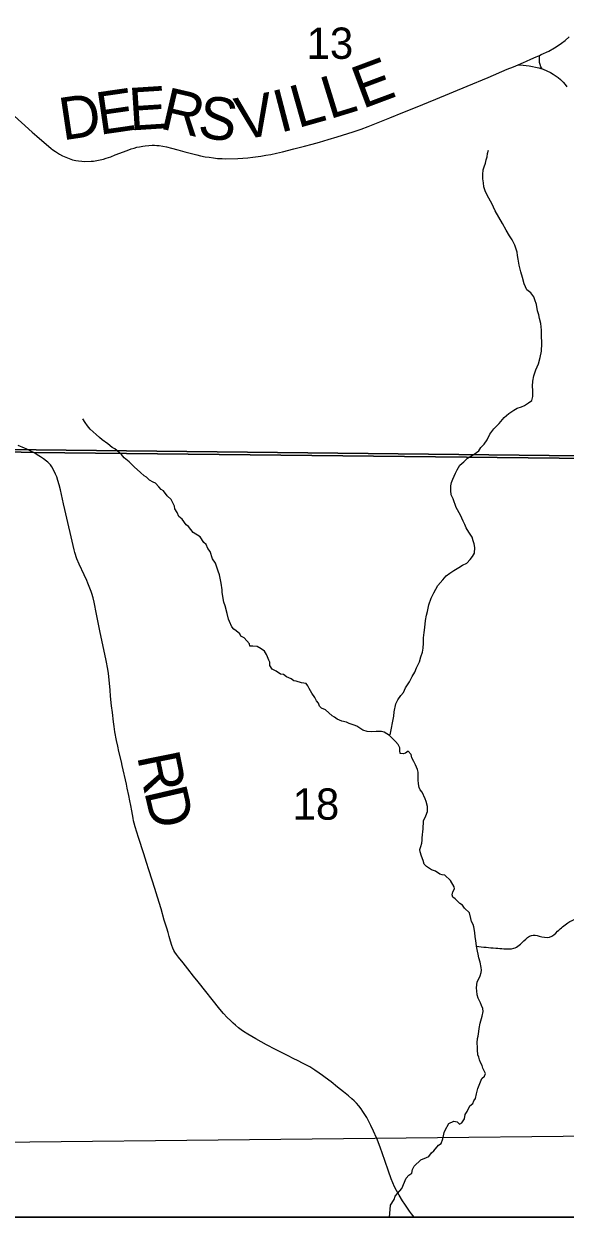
# Model space of a CAD drawing. Extents: x 0 to 34, y 0 to 22.
# Drawn here: x 21.301 to 22.024, y 13.6 to 15.196 of the extents above; entities that cross this region are included whole.
import ezdxf

# ---------------------------------------------------------------- set-up
doc = ezdxf.new("R2010")
doc.units = 0
for name, color, linetype in [('GM_X_Corporation', 7, 'Continuous'), ('GM_X_County_Road', 7, 'Continuous'), ('GM_X_County_Road_Text', 7, 'Continuous'), ('GM_X_Minor_River', 7, 'Continuous'), ('GM_X_Section_Text', 7, 'Continuous'), ('GM_X_Township_Road', 7, 'Continuous'), ('GM_X_Township_Road_Text', 7, 'Continuous'), ('SH_Data', 7, 'Continuous')]:
    doc.layers.add(name, color=color, linetype=linetype)

msp = doc.modelspace()

# ---------------------------------------------------------------- linework, layer by layer
at = {"layer": 'GM_X_Corporation'}
msp.add_lwpolyline([(20.2208, 16.9558), (20.1987, 15.2691), (20.203, 14.81), (20.2016, 14.6512), (20.2571, 14.6508), (21.1282, 14.6279), (21.314, 14.623), (22.3464, 14.612), (22.9003, 14.6033), (24.2301, 14.5912), (24.2265, 14.4444), (24.4406, 14.442), (25.338, 14.4317), (25.4, 14.4307), (25.4, 19.0068)], dxfattribs=at)
for points in [[(22.2224, 15.6282), (22.2045, 14.6168), (21.1958, 14.6279), (21.2159, 15.6439)], [(18.6, 14.6606), (18.6, 13.6), (24.2109, 13.6), (24.2228, 14.2453), (24.2265, 14.4444), (24.2301, 14.5912), (22.9003, 14.6033), (22.3464, 14.612), (21.314, 14.623), (21.1282, 14.6279), (20.2571, 14.6508), (20.2016, 14.6512), (19.8855, 14.6528), (19.4007, 14.6554), (18.9216, 14.6592)], [(21.1958, 14.6279), (22.2045, 14.6168), (22.1889, 13.7096), (21.1828, 13.6991)], [(21.1814, 13.6), (22.1867, 13.6), (22.1889, 13.7096), (21.1828, 13.6991)]]:
    msp.add_lwpolyline(points, close=True, dxfattribs=at)
at = {"layer": 'GM_X_County_Road'}
for points in [[(21.9616, 15.1415), (21.9686, 15.1447), (21.9724, 15.1464), (21.9783, 15.149), (21.9853, 15.1521), (21.9899, 15.1542), (21.992, 15.1552), (22.0025, 15.1601), (22.01, 15.1644), (22.0149, 15.1675), (22.0194, 15.1706), (22.024, 15.174), (22.0296, 15.179)], [(21.9933, 15.1362), (21.9918, 15.139), (21.9907, 15.1419), (21.9901, 15.1448), (21.9898, 15.1478), (21.9897, 15.1512), (21.9899, 15.1542)], [(21.2836, 15.0774), (21.3119, 15.0517), (21.3182, 15.0463), (21.3375, 15.0297), (21.3396, 15.0281), (21.3429, 15.0257), (21.347, 15.0229), (21.3486, 15.0221), (21.3525, 15.0199), (21.3567, 15.0179), (21.3615, 15.0161), (21.3658, 15.0147), (21.3703, 15.0137), (21.374, 15.013), (21.3783, 15.0125), (21.3825, 15.0123), (21.3908, 15.0125), (21.3937, 15.0129), (21.3982, 15.0136), (21.4028, 15.0145), (21.4071, 15.0156), (21.4107, 15.0168), (21.417, 15.0187), (21.4227, 15.0212), (21.4388, 15.027), (21.4443, 15.029), (21.4481, 15.0302), (21.4519, 15.0313), (21.4554, 15.0321), (21.4596, 15.0328), (21.463, 15.0333), (21.4678, 15.0338), (21.4722, 15.034), (21.4754, 15.0339), (21.4787, 15.0338), (21.4817, 15.0335), (21.4864, 15.0329), (21.4913, 15.0319), (21.498, 15.0302), (21.5064, 15.028), (21.5158, 15.0254), (21.5266, 15.0225), (21.5321, 15.021), (21.5369, 15.02), (21.5431, 15.0187), (21.5486, 15.0179), (21.5544, 15.017), (21.5598, 15.0165), (21.5659, 15.0161), (21.5706, 15.016), (21.5868, 15.0163), (21.5936, 15.0167), (21.6002, 15.0173), (21.607, 15.018), (21.6176, 15.0195), (21.6244, 15.0206), (21.6308, 15.0218), (21.6383, 15.0233), (21.6465, 15.0252), (21.6614, 15.029), (21.6759, 15.0326), (21.686, 15.0354), (21.6958, 15.0382), (21.7074, 15.0415), (21.7194, 15.0451), (21.741, 15.052), (21.7517, 15.0557), (21.7608, 15.0591), (21.79, 15.0708), (21.8073, 15.0778), (21.8244, 15.0847), (21.8512, 15.0956), (21.8933, 15.1129), (21.9214, 15.1248), (21.9469, 15.1356), (21.955, 15.1389), (21.9616, 15.1415)], [(21.9616, 15.1415), (21.968, 15.141), (21.9722, 15.1405), (21.9761, 15.1401), (21.9806, 15.1393), (21.9845, 15.1386), (21.989, 15.1376), (21.9918, 15.1367), (21.9933, 15.1362), (21.995, 15.1356), (21.9999, 15.1334), (22.0044, 15.1313), (22.0083, 15.129), (22.0122, 15.1265), (22.0147, 15.1246), (22.0181, 15.1218), (22.0214, 15.1186), (22.0241, 15.1151), (22.0263, 15.1121)]]:
    msp.add_lwpolyline(points, dxfattribs=at)
at = {"layer": 'GM_X_Minor_River'}
for points in [[(21.9615, 14.8818), (21.9603, 14.8867), (21.9599, 14.8909), (21.9571, 14.9004), (21.9532, 14.9076), (21.9497, 14.9128), (21.9454, 14.9204), (21.9404, 14.9295), (21.9354, 14.9378), (21.9307, 14.9461), (21.926, 14.9559), (21.9202, 14.9665), (21.9171, 14.9729), (21.9155, 14.9782), (21.915, 14.9836), (21.9142, 14.9889), (21.9141, 14.995), (21.9148, 15.0011), (21.9159, 15.0053), (21.9177, 15.0099), (21.9188, 15.0145), (21.9198, 15.0187), (21.9205, 15.0229), (21.9216, 15.0275)], [(21.7904, 14.2451), (21.7952, 14.2702), (21.7955, 14.2759), (21.798, 14.2866), (21.8006, 14.292), (21.8047, 14.2978), (21.808, 14.302), (21.811, 14.3081), (21.8161, 14.3162), (21.8198, 14.3235), (21.8232, 14.3289), (21.8257, 14.335), (21.8294, 14.3427), (21.8312, 14.3496), (21.8334, 14.3557), (21.8344, 14.3614), (21.8347, 14.3679), (21.835, 14.3752), (21.836, 14.382), (21.8367, 14.3889), (21.8377, 14.3984), (21.8391, 14.4053), (21.8402, 14.4103), (21.8419, 14.4191), (21.8452, 14.4282), (21.8489, 14.4352), (21.8541, 14.4451), (21.8608, 14.4525), (21.8652, 14.4579), (21.8701, 14.4614), (21.8754, 14.4649), (21.8821, 14.4692), (21.887, 14.4723), (21.8926, 14.4747), (21.8971, 14.4797), (21.9005, 14.4839), (21.903, 14.4885), (21.9033, 14.4958), (21.9025, 14.5007), (21.9013, 14.5049), (21.9001, 14.5098), (21.8954, 14.5166), (21.892, 14.5223), (21.89, 14.5268), (21.888, 14.5313), (21.8845, 14.5393), (21.8787, 14.5495), (21.8744, 14.5608), (21.872, 14.5665), (21.8716, 14.5719), (21.8715, 14.5783), (21.8722, 14.5829), (21.874, 14.5871), (21.8777, 14.5952), (21.8799, 14.5998), (21.8836, 14.6059), (21.8888, 14.6106), (21.8937, 14.6156), (21.8982, 14.618), (21.9027, 14.6207), (21.9087, 14.6254), (21.9113, 14.6296), (21.9161, 14.6342), (21.9198, 14.64), (21.9235, 14.6473), (21.9291, 14.6546), (21.9358, 14.6616), (21.9429, 14.6697), (21.9489, 14.6751), (21.9556, 14.6794), (21.9601, 14.6821), (21.9658, 14.6841), (21.9699, 14.6857), (21.9752, 14.6892), (21.9797, 14.6927), (21.9811, 14.6977), (21.981, 14.7061), (21.9805, 14.7118), (21.9808, 14.7183), (21.9822, 14.7255), (21.9848, 14.7336), (21.9884, 14.7416), (21.991, 14.75), (21.9927, 14.7584), (21.993, 14.7687), (21.9928, 14.7801), (21.9924, 14.7866), (21.9915, 14.7954), (21.9899, 14.8022), (21.989, 14.8071), (21.9874, 14.8124), (21.9858, 14.8208), (21.9838, 14.8272), (21.9823, 14.8314), (21.9784, 14.8367), (21.973, 14.8408), (21.9695, 14.8484), (21.9671, 14.8571), (21.9648, 14.8647), (21.9627, 14.8734), (21.9615, 14.8818)], [(21.7322, 14.2621), (21.7257, 14.2635), (21.7196, 14.2664), (21.7161, 14.2689), (21.7127, 14.2708), (21.7041, 14.2786), (21.6984, 14.2807), (21.6961, 14.2837), (21.6945, 14.2875), (21.6917, 14.2908), (21.6897, 14.2954), (21.6858, 14.301), (21.6819, 14.3074), (21.6803, 14.3107), (21.6783, 14.3137), (21.6719, 14.3147), (21.6646, 14.3172), (21.6616, 14.3175), (21.6581, 14.3201), (21.652, 14.323), (21.6477, 14.326), (21.6439, 14.3266), (21.6378, 14.3303), (21.6328, 14.3332), (21.6296, 14.3381), (21.6295, 14.3423), (21.628, 14.3453), (21.6263, 14.3494), (21.6251, 14.3525), (21.6224, 14.3573), (21.6181, 14.3603), (21.6128, 14.3636), (21.6067, 14.3638), (21.6029, 14.3637), (21.6024, 14.3672), (21.5951, 14.375), (21.5908, 14.3772), (21.5893, 14.3802), (21.5846, 14.3842), (21.5815, 14.3865), (21.5788, 14.3898), (21.5756, 14.397), (21.5744, 14.4), (21.5723, 14.4076), (21.5698, 14.4178), (21.5682, 14.4227), (21.5669, 14.4303), (21.566, 14.436), (21.5659, 14.4394), (21.5646, 14.4481), (21.5637, 14.4527), (21.5624, 14.4591), (21.5604, 14.464), (21.5567, 14.475), (21.5528, 14.4806), (21.5499, 14.4904), (21.5468, 14.4945), (21.5444, 14.4998), (21.5413, 14.5024), (21.5366, 14.5103), (21.527, 14.5161), (21.5207, 14.524), (21.5176, 14.5262), (21.5122, 14.5337), (21.5079, 14.5374), (21.5059, 14.5427), (21.5027, 14.5476), (21.5019, 14.551), (21.4975, 14.56), (21.4925, 14.5648), (21.4874, 14.5716), (21.4843, 14.5734), (21.4812, 14.5771), (21.4766, 14.582), (21.4735, 14.5834), (21.4685, 14.586), (21.4646, 14.5901), (21.4616, 14.5919), (21.4569, 14.596), (21.448, 14.6038), (21.4414, 14.6105), (21.4349, 14.616), (21.4313, 14.6205), (21.4225, 14.6279), (21.419, 14.6297), (21.4132, 14.6346), (21.4055, 14.6397), (21.402, 14.643), (21.3974, 14.6471), (21.3896, 14.6542), (21.3858, 14.6587), (21.3826, 14.6632), (21.3795, 14.668)], [(21.9069, 13.827), (21.9064, 13.8331), (21.907, 13.8392), (21.9081, 13.8422), (21.9087, 13.8483), (21.9093, 13.8525), (21.9107, 13.8594), (21.9114, 13.8625), (21.9135, 13.869), (21.9145, 13.8751), (21.914, 13.8789), (21.9124, 13.8831), (21.9112, 13.8865), (21.908, 13.8928), (21.9067, 13.8974), (21.9062, 13.9027), (21.9058, 13.9065), (21.906, 13.9111), (21.9067, 13.9145), (21.9107, 13.923), (21.9121, 13.9272), (21.9124, 13.9306), (21.9119, 13.934), (21.9106, 13.9409), (21.909, 13.9469), (21.9081, 13.9518), (21.9069, 13.956), (21.9056, 13.9624), (21.905, 13.97), (21.9041, 13.975), (21.9036, 13.9807), (21.9023, 13.9882), (21.9011, 13.9913), (21.8991, 13.9954), (21.8983, 13.9996), (21.8962, 14.0071), (21.8896, 14.0134), (21.8869, 14.0172), (21.8834, 14.0198), (21.8772, 14.0257), (21.8741, 14.0279), (21.8733, 14.0313), (21.8743, 14.0352), (21.8765, 14.039), (21.876, 14.0421), (21.8709, 14.0503), (21.8635, 14.0577), (21.8597, 14.058), (21.8567, 14.0587), (21.8509, 14.0628), (21.8456, 14.0646), (21.8387, 14.069), (21.8359, 14.0723), (21.8343, 14.0772), (21.8323, 14.0829), (21.8306, 14.0886), (21.8302, 14.092), (21.8312, 14.0958), (21.8326, 14.1004), (21.8329, 14.1042), (21.8332, 14.1073), (21.8335, 14.1115), (21.8341, 14.1157), (21.8344, 14.1191), (21.8349, 14.1302), (21.8378, 14.1367), (21.8403, 14.1428), (21.8402, 14.1493), (21.8385, 14.1561), (21.8369, 14.1595), (21.8329, 14.1686), (21.8305, 14.1715), (21.8289, 14.1749), (21.8284, 14.1799), (21.8276, 14.1852), (21.8277, 14.1955), (21.8269, 14.1989), (21.8244, 14.2049), (21.8221, 14.2094), (21.8193, 14.2143), (21.8184, 14.2188), (21.8145, 14.2233), (21.8108, 14.2206), (21.8078, 14.2197), (21.8036, 14.2204), (21.8032, 14.2242), (21.8031, 14.228), (21.8011, 14.2321), (21.7976, 14.2362), (21.7941, 14.24), (21.7894, 14.2444), (21.7825, 14.2488), (21.7787, 14.2499), (21.7715, 14.2497), (21.7651, 14.2492), (21.7597, 14.2498), (21.754, 14.2516), (21.7456, 14.2567), (21.7421, 14.2581), (21.7356, 14.2603), (21.7322, 14.2621)], [(21.7896, 13.6), (21.7899, 13.605), (21.7908, 13.616), (21.7959, 13.6234), (21.7969, 13.628), (21.8032, 13.635), (21.8058, 13.6381), (21.8115, 13.6523), (21.8155, 13.6562), (21.8193, 13.659), (21.8203, 13.6636), (21.8225, 13.6682), (21.8313, 13.6768), (21.8389, 13.6796), (21.8422, 13.6812), (21.8455, 13.6862), (21.8485, 13.6886), (21.8551, 13.6963), (21.8585, 13.6983), (21.8606, 13.7049), (21.8616, 13.7087), (21.8627, 13.7133), (21.8637, 13.7163), (21.8688, 13.7252), (21.8756, 13.7284), (21.8798, 13.7274), (21.8832, 13.7244), (21.8862, 13.726), (21.8895, 13.7314), (21.8905, 13.7372), (21.8934, 13.7414), (21.8967, 13.7491), (21.9008, 13.7519), (21.9022, 13.7557), (21.9044, 13.7588), (21.9057, 13.7649), (21.9064, 13.7687), (21.9075, 13.7722), (21.9128, 13.7853), (21.9165, 13.7884), (21.9176, 13.7922), (21.9144, 13.7994), (21.9132, 13.8028), (21.9112, 13.8069), (21.9096, 13.8103), (21.9087, 13.8141), (21.9075, 13.8171), (21.907, 13.8236), (21.9069, 13.827)]]:
    msp.add_lwpolyline(points, dxfattribs=at)
msp.add_spline([(21.9056, 13.9624), (21.9314, 13.9599), (21.9424, 13.9591), (21.9557, 13.9597), (21.9691, 13.9698), (21.9791, 13.9769), (21.9893, 13.976), (22.0034, 13.9747), (22.0141, 13.9825), (22.0279, 13.9938), (22.0393, 13.999), (22.0519, 14.0003), (22.0634, 14.007), (22.0726, 14.0176), (22.0838, 14.033), (22.0908, 14.0439), (22.0966, 14.0583), (22.1005, 14.0681), (22.1056, 14.0783), (22.1122, 14.0896), (22.1188, 14.0998), (22.1314, 14.1107), (22.1437, 14.1227), (22.1533, 14.1313), (22.1663, 14.1395), (22.1763, 14.1424), (22.188, 14.1423), (22.2005, 14.1399), (22.2149, 14.1333), (22.2256, 14.1381), (22.2363, 14.1467), (22.2459, 14.1542), (22.2578, 14.1635), (22.2682, 14.1741), (22.2782, 14.1846), (22.2867, 14.197), (22.294, 14.2091), (22.2987, 14.22), (22.3046, 14.2317), (22.3096, 14.2435), (22.3136, 14.254), (22.3164, 14.2669), (22.3191, 14.2768), (22.3212, 14.287), (22.3278, 14.3002), (22.3393, 14.313), (22.3479, 14.3277), (22.3537, 14.3413), (22.361, 14.3511), (22.3695, 14.3624), (22.3792, 14.3756), (22.3744, 14.3878), (22.376, 14.3984), (22.3823, 14.4108)], degree=3, dxfattribs=at)
at = {"layer": 'GM_X_Township_Road'}
for points in [[(21.3017, 14.6288), (21.2934, 14.6323)], [(21.8224, 13.6), (21.819, 13.6042), (21.8162, 13.608), (21.8098, 13.6173), (21.8068, 13.6219), (21.8022, 13.6295), (21.7987, 13.6357), (21.7962, 13.6405), (21.7938, 13.6457), (21.7918, 13.6512), (21.7883, 13.6614), (21.7833, 13.6759), (21.7771, 13.6935), (21.7733, 13.7028), (21.772, 13.7061), (21.7682, 13.715), (21.7647, 13.7225), (21.7606, 13.7306), (21.759, 13.7335), (21.7567, 13.7374), (21.7539, 13.7415), (21.7514, 13.7451), (21.7484, 13.7489), (21.7454, 13.7523), (21.7421, 13.7557), (21.7392, 13.7584), (21.7348, 13.7621), (21.7279, 13.7676), (21.7199, 13.7737), (21.7113, 13.7809), (21.7035, 13.787), (21.6999, 13.7897), (21.6955, 13.7927), (21.6898, 13.7965), (21.6828, 13.8009), (21.6785, 13.8033), (21.6734, 13.806), (21.6675, 13.809), (21.6608, 13.8124), (21.6539, 13.8159), (21.648, 13.8188), (21.6373, 13.8242), (21.625, 13.8306), (21.6107, 13.8386), (21.6002, 13.8449), (21.5945, 13.8484), (21.5911, 13.8506), (21.5876, 13.8534), (21.5835, 13.8567), (21.5806, 13.8594), (21.5769, 13.8629), (21.5727, 13.8672), (21.5677, 13.8725), (21.5628, 13.8784), (21.5338, 13.9148), (21.5277, 13.9224), (21.5199, 13.9323), (21.5135, 13.9402), (21.5076, 13.9477), (21.5046, 13.9514), (21.5026, 13.9543), (21.5012, 13.9567), (21.4999, 13.9598), (21.4985, 13.9636), (21.4969, 13.9691), (21.4951, 13.9753), (21.4935, 13.9806), (21.4917, 13.9865), (21.4885, 13.9974), (21.4841, 14.0125), (21.4795, 14.028), (21.4758, 14.0396), (21.4723, 14.0506), (21.4678, 14.0645), (21.4646, 14.0744), (21.461, 14.086), (21.4542, 14.1077), (21.4496, 14.1221), (21.4482, 14.1269), (21.4474, 14.1301), (21.4467, 14.1338), (21.445, 14.1436), (21.4437, 14.1506), (21.4425, 14.1568), (21.441, 14.164), (21.4389, 14.174), (21.4378, 14.1792), (21.4322, 14.2042), (21.4311, 14.2091), (21.4277, 14.2231), (21.4262, 14.2302), (21.4247, 14.2375), (21.4225, 14.2494), (21.4213, 14.2562), (21.4205, 14.2627), (21.4191, 14.275), (21.4181, 14.2841), (21.4167, 14.2968), (21.416, 14.3051), (21.4143, 14.3231), (21.4138, 14.3275), (21.4129, 14.333), (21.4106, 14.3445), (21.4022, 14.3843), (21.3977, 14.4067), (21.3947, 14.4227), (21.3934, 14.4285), (21.3918, 14.4342), (21.3909, 14.4371), (21.3865, 14.4481), (21.3849, 14.4516), (21.3813, 14.4593), (21.3747, 14.4735), (21.3717, 14.4807), (21.369, 14.4891), (21.368, 14.4928), (21.3556, 14.5465), (21.3538, 14.5544), (21.3499, 14.573), (21.348, 14.5798), (21.3463, 14.5856), (21.3448, 14.5902), (21.3432, 14.5941), (21.3407, 14.5991), (21.338, 14.6037), (21.3362, 14.6063), (21.3345, 14.6083), (21.3328, 14.6099), (21.3309, 14.6115), (21.327, 14.6144), (21.323, 14.6172), (21.3188, 14.6199), (21.3146, 14.6224), (21.3064, 14.6267), (21.3038, 14.6279), (21.3017, 14.6288)]]:
    msp.add_lwpolyline(points, dxfattribs=at)
at = {"layer": 'SH_Data'}
msp.add_lwpolyline([(18.6, 20.4), (25.4, 20.4), (25.4, 13.6), (18.6, 13.6)], close=True, dxfattribs=at)

# ---------------------------------------------------------------- texts
at = {"layer": 'GM_X_County_Road_Text'}
for s, rotation, p in [('E', 20.5507, (21.7533, 15.0823)), ('L', 17.1353, (21.7092, 15.0686)), ('D', 8.4603, (21.3525, 15.0404)), ('E', 8.2786, (21.4019, 15.0478)), ('E', 3.6924, (21.4428, 15.0537)), ('R', 346.9814, (21.4808, 15.0568)), ('V', 10.4867, (21.5895, 15.0404)), ('I', 14.559, (21.643, 15.0504)), ('L', 15.7604, (21.6668, 15.0567)), ('S', 351.9332, (21.5316, 15.0453))]:
    msp.add_text(s, height=0.0568, rotation=rotation, dxfattribs=at).set_placement(p)
at = {"layer": 'GM_X_Section_Text'}
for s, p in [('13', (21.6787, 15.1496)), ('18', (21.66, 14.1317))]:
    msp.add_text(s, height=0.04186, rotation=0, dxfattribs=at).set_placement(p)
at = {"layer": 'GM_X_Township_Road_Text'}
for s, rotation, p in [('R', 281.4454, (21.4519, 14.2169)), ('D', 283.0767, (21.4615, 14.1694))]:
    msp.add_text(s, height=0.0568, rotation=rotation, dxfattribs=at).set_placement(p)

doc.saveas('drawing.dxf')
